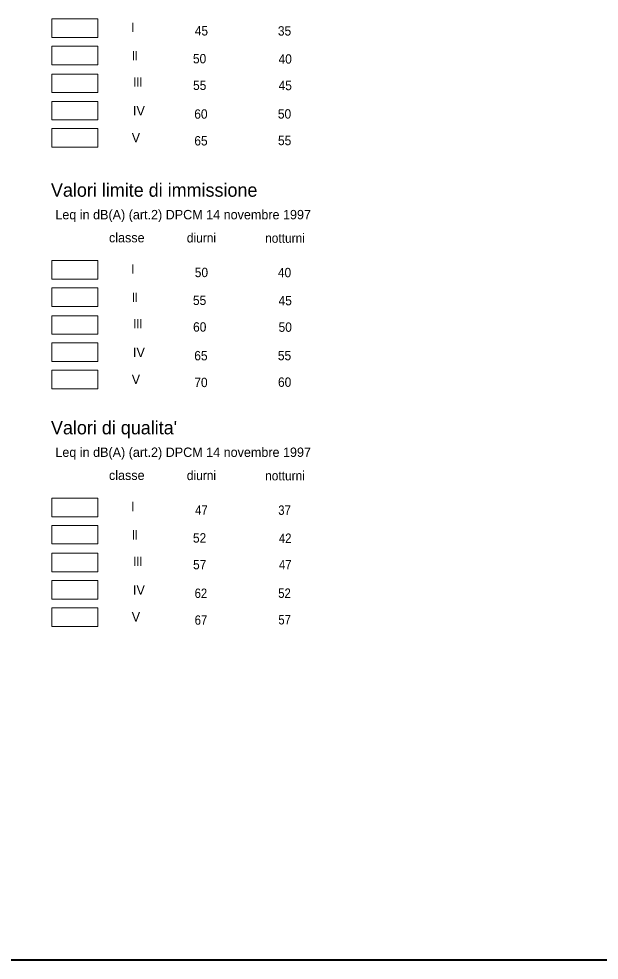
# Model space of a CAD drawing. Extents: x 650071 to 653841, y 889105 to 891996.
# Drawn here: x 651141 to 652006, y 889106 to 890509 of the extents above; entities that cross this region are included whole.
import ezdxf
from ezdxf.enums import TextEntityAlignment as Align

# ---------------------------------------------------------------- set-up
doc = ezdxf.new("R2010")
doc.units = 0
doc.header["$LTSCALE"] = 5.6
doc.layers.add('61', color=7, linetype='Continuous', lineweight=35)

msp = doc.modelspace()

# ---------------------------------------------------------------- linework, layer by layer
at = {"layer": '61', "lineweight": 40}
msp.add_line((652174.44, 889106.04), (650071.44, 889106.05), dxfattribs=at)
at = {"layer": '61', "lineweight": 13}
for points in [[(651190.02, 890509.39), (651258.56, 890509.39), (651258.56, 890481.67), (651190.02, 890481.67)], [(651190.02, 890468.69), (651258.56, 890468.69), (651258.56, 890440.97), (651190.02, 890440.97)], [(651190.02, 890427.11), (651258.56, 890427.11), (651258.56, 890399.39), (651190.02, 890399.39)], [(651190.02, 890386.39), (651258.56, 890386.39), (651258.56, 890358.67), (651190.02, 890358.67)], [(651190.02, 890345.67), (651258.56, 890345.67), (651258.56, 890317.95), (651190.02, 890317.95)], [(651190.02, 890149.13), (651258.56, 890149.13), (651258.56, 890121.41), (651190.02, 890121.41)], [(651190.02, 890108.43), (651258.56, 890108.43), (651258.56, 890080.71), (651190.02, 890080.71)], [(651190.02, 890066.85), (651258.56, 890066.85), (651258.56, 890039.13), (651190.02, 890039.13)], [(651190.02, 890026.13), (651258.56, 890026.13), (651258.56, 889998.41), (651190.02, 889998.41)], [(651190.02, 889985.41), (651258.56, 889985.41), (651258.56, 889957.69), (651190.02, 889957.69)], [(651190.02, 889794.92), (651258.56, 889794.92), (651258.56, 889767.2), (651190.02, 889767.2)], [(651190.02, 889754.22), (651258.56, 889754.22), (651258.56, 889726.5), (651190.02, 889726.5)], [(651190.02, 889712.64), (651258.56, 889712.64), (651258.56, 889684.92), (651190.02, 889684.92)], [(651190.02, 889671.92), (651258.56, 889671.92), (651258.56, 889644.2), (651190.02, 889644.2)], [(651190.02, 889631.2), (651258.56, 889631.2), (651258.56, 889603.48), (651190.02, 889603.48)]]:
    msp.add_lwpolyline(points, close=True, dxfattribs=at)

# ---------------------------------------------------------------- texts
at = {"layer": '61'}
for s, p in [('I', (651310.65, 890489.89)), ('IV', (651319.73, 890365.33)), ('V', (651315.24, 890325.39)), ('classe', (651301.63, 890176.16)), ('I', (651310.65, 890129.63)), ('IV', (651319.73, 890005.07)), ('V', (651315.24, 889965.13)), ('classe', (651301.63, 889821.94)), ('I', (651310.65, 889775.41)), ('IV', (651319.73, 889650.85)), ('V', (651315.24, 889610.91))]:
    msp.add_text(s, height=14, dxfattribs=at).set_placement(p, align=Align.CENTER)
for s, width, p in [('45', 0.95, (651412.85, 890484.56)), ('35', 0.95, (651536.69, 890484.38)), ('II', 0.8, (651313.59, 890447.57)), (' 50', 0.95, (651407.64, 890443.02)), ('40', 0.95, (651537.68, 890442.58)), ('III', 0.85, (651318.19, 890408.27)), (' 55', 0.95, (651407.82, 890403.3)), ('45', 0.95, (651537.71, 890403.04)), ('60', 0.95, (651412.09, 890360.5)), ('50', 0.95, (651536.68, 890360.64)), ('65', 0.95, (651412.16, 890320.6)), ('55', 0.95, (651536.85, 890321.02)), ('diurni', 0.95, (651412.84, 890175.96)), ('notturni', 0.95, (651537.41, 890175.52)), ('50', 0.95, (651412.85, 890124.3)), ('40', 0.95, (651536.69, 890124.12)), ('II', 0.8, (651313.59, 890087.31)), (' 55', 0.95, (651407.64, 890082.76)), ('45', 0.95, (651537.68, 890082.32)), ('III', 0.85, (651318.19, 890048.01)), (' 60', 0.95, (651407.82, 890043.04)), ('50', 0.95, (651537.71, 890042.78)), ('65', 0.95, (651412.09, 890000.24)), ('55', 0.95, (651536.68, 890000.38)), ('70', 0.95, (651412.16, 889960.34)), ('60', 0.95, (651536.85, 889960.76)), ('diurni', 0.95, (651412.84, 889821.74)), ('notturni', 0.95, (651537.41, 889821.3)), ('47', 0.9, (651412.85, 889770.08)), ('37', 0.9, (651536.69, 889769.9)), ('II', 0.8, (651313.59, 889733.09)), (' 52', 0.95, (651407.65, 889728.54)), ('42', 0.9, (651537.67, 889728.1)), ('III', 0.85, (651318.19, 889693.79)), (' 57', 0.95, (651407.82, 889688.82)), ('47', 0.9, (651537.71, 889688.56)), ('62', 0.9, (651412.09, 889646.02)), ('52', 0.9, (651536.67, 889646.16)), ('67', 0.9, (651412.15, 889606.12)), ('57', 0.9, (651536.85, 889606.54))]:
    msp.add_text(s, height=14, dxfattribs=dict(at, width=width)).set_placement(p, align=Align.CENTER)
for s, height, p in [('Valori limite di immissione', 20, (651188.64, 890244.16)), ('Leq in dB(A) (art.2) DPCM 14 novembre 1997', 14, (651195.22, 890210.48)), ("Valori di qualita'", 20, (651188.64, 889889.94)), ('Leq in dB(A) (art.2) DPCM 14 novembre 1997', 14, (651195.22, 889856.26))]:
    msp.add_text(s, height=height, dxfattribs=at).set_placement(p)

doc.saveas('drawing.dxf')
